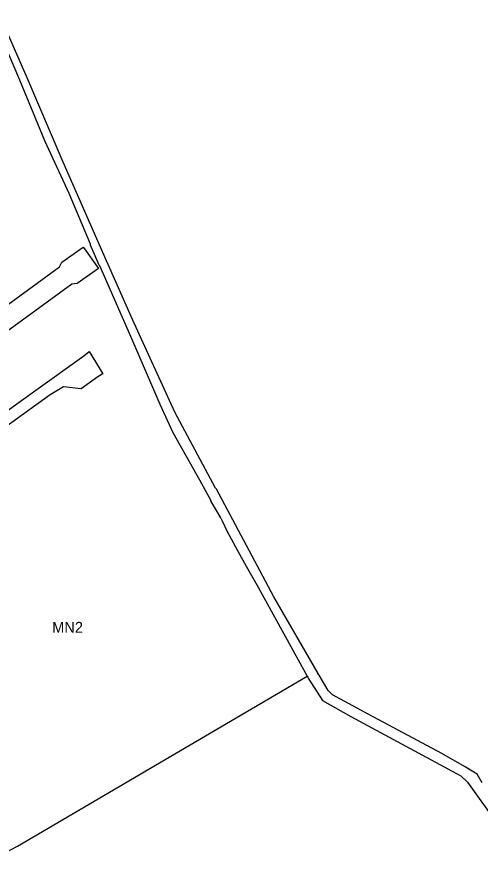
# Model space of a CAD drawing. Extents: x 7435758 to 7439981, y 5550649 to 5554049.
# Drawn here: x 7437850.9 to 7438071.5, y 5551546.4 to 5551945.9 of the extents above; entities that cross this region are included whole.
import ezdxf

# ---------------------------------------------------------------- set-up
doc = ezdxf.new("R2010")
doc.units = 0
doc.layers.add('linie_rozgraniczające', color=7, linetype='Continuous')
doc.layers.add('oznaczenia_przeznaczen', color=7, linetype='Continuous')

msp = doc.modelspace()

# ---------------------------------------------------------------- linework, layer by layer
at = {"layer": 'linie_rozgraniczające'}
for p, q in [((7437855.94, 5551916.89), (7437843.13, 5551945.94)), ((7437840.36, 5551943.66), (7437852.28, 5551915.86)), ((7437873.07, 5551876.82), (7437855.94, 5551916.89)), ((7437852.28, 5551915.86), (7437864.12, 5551887.06)), ((7437864.12, 5551887.06), (7437875.74, 5551862.03)), ((7437893.59, 5551829.8), (7437873.07, 5551876.82)), ((7437875.74, 5551862.03), (7437885.84, 5551837.94)), ((7437885.84, 5551837.94), (7437885.85, 5551837.43)), ((7437885.85, 5551837.43), (7437889.97, 5551827.94)), ((7437872.36, 5551829.12), (7437882.54, 5551836.36)), ((7437882.54, 5551836.36), (7437883.17, 5551835.49)), ((7437883.17, 5551835.49), (7437889.03, 5551827.25)), ((7437871.35, 5551826.92), (7437872.36, 5551829.12)), ((7437893.52, 5551829.77), (7437893.59, 5551829.8)), ((7437893.73, 5551829.5), (7437893.52, 5551829.77)), ((7437906.03, 5551801.93), (7437893.73, 5551829.5)), ((7437807.11, 5551780.31), (7437871.35, 5551826.92)), ((7437889.79, 5551826.18), (7437879.61, 5551818.93)), ((7437889.03, 5551827.25), (7437889.79, 5551826.18)), ((7437889.97, 5551827.94), (7437890.35, 5551827.58)), ((7437890.35, 5551827.58), (7437905.06, 5551793.87)), ((7437877.2, 5551818.71), (7437812.75, 5551772.12)), ((7437879.61, 5551818.93), (7437877.2, 5551818.71)), ((7437926.23, 5551757.79), (7437906.03, 5551801.93)), ((7437905.06, 5551793.87), (7437918.96, 5551761.62)), ((7437882.93, 5551784.61), (7437885.38, 5551786.59)), ((7437885.38, 5551786.59), (7437891.82, 5551775.94)), ((7437860.01, 5551768.18), (7437882.93, 5551784.61)), ((7437889.51, 5551774.56), (7437881.54, 5551768.85)), ((7437891.82, 5551775.94), (7437889.51, 5551774.56)), ((7437873.16, 5551769.78), (7437866.87, 5551766.02)), ((7437881.54, 5551768.85), (7437873.16, 5551769.78)), ((7437866.87, 5551766.02), (7437819.07, 5551731.54)), ((7437832.18, 5551748.17), (7437860.01, 5551768.18)), ((7437918.96, 5551761.62), (7437925.15, 5551748.04)), ((7437945.52, 5551721.51), (7437926.23, 5551757.79)), ((7437925.15, 5551748.04), (7437937.86, 5551725.48)), ((7437937.86, 5551725.48), (7437943.28, 5551715.71)), ((7437945.97, 5551721.06), (7437945.52, 5551721.51)), ((7437973.32, 5551669.86), (7437945.97, 5551721.06)), ((7437943.28, 5551715.71), (7437943.28, 5551715.19)), ((7437943.28, 5551715.19), (7437943.33, 5551715.23)), ((7437943.33, 5551715.23), (7437943.81, 5551714.42)), ((7437943.81, 5551714.42), (7437947.91, 5551707.42)), ((7437947.91, 5551707.42), (7437948.02, 5551707.38)), ((7437948.02, 5551707.38), (7437948.37, 5551706.64)), ((7437948.37, 5551706.64), (7437948.69, 5551706.09)), ((7437948.69, 5551706.09), (7437948.64, 5551706.06)), ((7437948.64, 5551706.06), (7437951.04, 5551700.99)), ((7437951.04, 5551700.99), (7437956.99, 5551690.23)), ((7437956.99, 5551690.23), (7437960.16, 5551684.51)), ((7437960.16, 5551684.51), (7437965.11, 5551675.57)), ((7437965.11, 5551675.57), (7437968.45, 5551669.53)), ((7437968.45, 5551669.53), (7437989.21, 5551632.03)), ((7437994.32, 5551633.42), (7437973.32, 5551669.86)), ((7437994.22, 5551633.38), (7437994.32, 5551633.42)), ((7437994.84, 5551632.59), (7437994.22, 5551633.38)), ((7437851.26, 5551551.21), (7437989.21, 5551632.03)), ((7437989.21, 5551632.03), (7437989.4, 5551631.69)), ((7437989.4, 5551631.69), (7437989.65, 5551631.23)), ((7437989.65, 5551631.23), (7437989.67, 5551631.09)), ((7437989.67, 5551631.09), (7437996.42, 5551620.51)), ((7437999.09, 5551625.26), (7437994.84, 5551632.59)), ((7438001.14, 5551623.17), (7437999.09, 5551625.26)), ((7438018.49, 5551613.81), (7438001.14, 5551623.17)), ((7437996.42, 5551620.51), (7438009.94, 5551612.97)), ((7438053.19, 5551595.29), (7438018.49, 5551613.81)), ((7438009.94, 5551612.97), (7438062.2, 5551584.7)), ((7438063.99, 5551589.12), (7438053.19, 5551595.29)), ((7438068.41, 5551586.43), (7438063.99, 5551589.12)), ((7438070.07, 5551585.42), (7438068.41, 5551586.43)), ((7438072.4, 5551581.37), (7438070.07, 5551585.42)), ((7438062.2, 5551584.7), (7438065.48, 5551581.68)), ((7438065.48, 5551581.68), (7438078.66, 5551563.27)), ((7437842.06, 5551546.41), (7437851.26, 5551551.21))]:
    msp.add_line(p, q, dxfattribs=at)

# ---------------------------------------------------------------- texts
at = {"layer": 'oznaczenia_przeznaczen'}
msp.add_text('MN2', height=5.2, dxfattribs=at).set_placement((7437867.77, 5551652.74))

doc.saveas('drawing.dxf')
